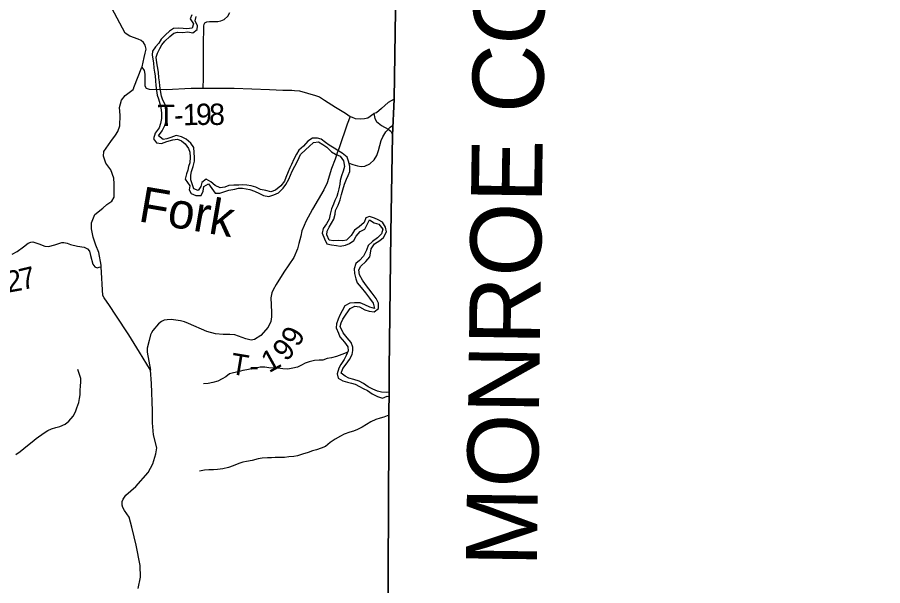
# Model space of a CAD drawing. Extents: x 2043100 to 2470832, y 443715 to 810583.
# Drawn here: x 2296048 to 2308244, y 667437 to 675442 of the extents above; entities that cross this region are included whole.
import ezdxf

# ---------------------------------------------------------------- set-up
doc = ezdxf.new("R2010")
doc.units = 0
for name, color, linetype in [('GM_X_Adjacent_County', 7, 'Continuous'), ('GM_X_Adjacent_County_Text', 7, 'Continuous'), ('GM_X_County', 7, 'Continuous'), ('GM_X_Minor_River', 7, 'Continuous'), ('GM_X_Minor_River_Text', 7, 'Continuous'), ('GM_X_State_Route', 7, 'Continuous'), ('GM_X_Township', 7, 'Continuous'), ('GM_X_Township_Road', 7, 'Continuous'), ('GM_X_Township_Road_Text', 7, 'Continuous'), ('GM_X_Township_ROW', 7, 'Continuous')]:
    doc.layers.add(name, color=color, linetype=linetype)

msp = doc.modelspace()

# ---------------------------------------------------------------- linework, layer by layer
at = {"layer": 'GM_X_Adjacent_County'}
msp.add_lwpolyline([(2300714, 629163), (2300774, 635425), (2300814, 639567), (2300926, 645360), (2300953, 646723), (2300982, 648198), (2301002, 649256), (2301016, 650156), (2301098, 653379), (2301153, 655541), (2301153, 656155), (2301254, 663815), (2301288, 670486), (2301311, 672396), (2301315, 672683), (2301334, 673782), (2301360, 674291), (2301434, 679295), (2301452, 681110), (2301478, 683091), (2302497, 683068), (2305696, 683037), (2309205, 683004)], dxfattribs=at)
at = {"layer": 'GM_X_County'}
msp.add_lwpolyline([(2309205, 683004), (2305696, 683037), (2302497, 683068), (2301478, 683091), (2301452, 681110), (2301434, 679295), (2301360, 674291), (2301334, 673782), (2301315, 672683), (2301311, 672396), (2301288, 670486), (2301254, 663815), (2301153, 656155), (2301153, 655541), (2301098, 653379), (2301016, 650156), (2301002, 649256), (2300982, 648198), (2300953, 646723), (2300926, 645360), (2300814, 639567), (2300774, 635425), (2300714, 629163)], dxfattribs=at)
at = {"layer": 'GM_X_Minor_River'}
msp.add_line((2301288, 670100), (2301289, 670163), dxfattribs=at)
for points in [[(2298537, 673607), (2298494, 673671), (2298426, 673724), (2298362, 673760), (2298286, 673776), (2298210, 673751), (2298156, 673731), (2298104, 673722), (2298036, 673772), (2298088, 673842), (2298125, 673917), (2298147, 673979), (2298152, 674051), (2298146, 674103), (2298138, 674165), (2298131, 674215), (2298097, 674277), (2298081, 674333), (2298066, 674413), (2298058, 674477), (2298050, 674533), (2298043, 674589), (2298037, 674667), (2298024, 674751), (2298016, 674801), (2298006, 674879), (2298025, 674938), (2298057, 675002), (2298087, 675054), (2298126, 675107), (2298196, 675173), (2298252, 675219), (2298307, 675234), (2298379, 675226), (2298449, 675235), (2298521, 675223), (2298583, 675268), (2298587, 675322), (2298554, 675392), (2298570, 675452)], [(2298506, 675475), (2298486, 675421), (2298529, 675351), (2298513, 675291), (2298439, 675281), (2298385, 675286), (2298321, 675288), (2298249, 675282), (2298195, 675247), (2298138, 675195), (2298076, 675132)], [(2298076, 675132), (2298041, 675078), (2297995, 675026), (2297953, 674965), (2297948, 674915), (2297958, 674851), (2297968, 674801), (2297971, 674725), (2297983, 674671), (2297991, 674619), (2297994, 674549), (2298000, 674481), (2298017, 674345), (2298037, 674293), (2298055, 674229), (2298072, 674167), (2298082, 674097), (2298081, 674019), (2298067, 673946), (2298047, 673884), (2297992, 673808), (2297968, 673732), (2298011, 673676), (2298081, 673666), (2298157, 673691), (2298238, 673715), (2298306, 673726), (2298360, 673700), (2298415, 673658), (2298459, 673596), (2298479, 673542), (2298486, 673474), (2298480, 673392), (2298460, 673342), (2298451, 673288), (2298433, 673238), (2298413, 673163), (2298478, 673070), (2298472, 673013), (2298500, 672962), (2298565, 672930), (2298637, 672930), (2298666, 672993), (2298678, 673059), (2298744, 673095), (2298790, 673031), (2298834, 672966), (2298904, 672966), (2298960, 672984), (2299030, 673007), (2299112, 673021), (2299164, 673036), (2299220, 673034), (2299272, 673028), (2299324, 673017), (2299390, 672995), (2299460, 672961), (2299518, 672934), (2299592, 672916), (2299662, 672940), (2299730, 672971), (2299795, 673035), (2299833, 673086), (2299876, 673164), (2299920, 673273), (2299959, 673345), (2300003, 673423), (2300038, 673510), (2300112, 673582), (2300163, 673623), (2300223, 673677), (2300291, 673687), (2300355, 673650), (2300409, 673612), (2300476, 673548), (2300530, 673515), (2300596, 673485), (2300646, 673421), (2300659, 673341), (2300639, 673275), (2300618, 673207), (2300600, 673144), (2300594, 673094), (2300579, 673024), (2300563, 672972), (2300551, 672920), (2300524, 672862), (2300502, 672811), (2300476, 672745), (2300459, 672669), (2300445, 672597), (2300406, 672532), (2300358, 672466), (2300346, 672400), (2300375, 672320), (2300411, 672250), (2300477, 672238), (2300545, 672227), (2300597, 672219), (2300675, 672234), (2300729, 672256)], [(2300724, 673390), (2300778, 673368), (2300841, 673348), (2300893, 673341), (2300946, 673345), (2301016, 673377), (2301076, 673434), (2301117, 673496), (2301137, 673566), (2301155, 673635), (2301176, 673709), (2301200, 673759), (2301241, 673827), (2301303, 673894), (2301335, 673919)], [(2301008, 671302), (2301078, 671294), (2301136, 671339), (2301140, 671417), (2301107, 671481), (2301051, 671559), (2301000, 671618), (2300954, 671678), (2300914, 671742), (2300871, 671814), (2300859, 671886), (2300891, 671936), (2300960, 672001), (2301016, 672067), (2301026, 672119), (2301033, 672182), (2301081, 672250), (2301156, 672297), (2301210, 672339), (2301252, 672419), (2301237, 672487), (2301195, 672557), (2301133, 672591), (2301081, 672615), (2301013, 672638), (2300961, 672616), (2300935, 672550), (2300865, 672491), (2300800, 672445), (2300752, 672370), (2300689, 672304), (2300635, 672295), (2300573, 672297), (2300505, 672295), (2300441, 672304), (2300412, 672380), (2300414, 672430), (2300442, 672488), (2300475, 672541), (2300507, 672597), (2300527, 672671), (2300534, 672721), (2300572, 672794), (2300597, 672870), (2300617, 672946), (2300637, 673012), (2300658, 673091), (2300686, 673161), (2300713, 673213), (2300733, 673269), (2300733, 673342), (2300722, 673402), (2300696, 673470), (2300628, 673527), (2300577, 673557), (2300513, 673599), (2300443, 673640), (2300393, 673678), (2300329, 673728), (2300279, 673741), (2300207, 673741), (2300141, 673699), (2300083, 673628), (2300014, 673570), (2299982, 673513), (2299943, 673445), (2299911, 673371), (2299891, 673320), (2299864, 673266), (2299834, 673186), (2299815, 673136), (2299761, 673067), (2299689, 673009), (2299620, 672984), (2299549, 673002), (2299475, 673019), (2299409, 673049), (2299343, 673067), (2299283, 673076), (2299227, 673082), (2299169, 673080), (2299099, 673079), (2299031, 673071), (2298972, 673051), (2298908, 673042), (2298834, 673072), (2298775, 673127), (2298709, 673161), (2298649, 673115), (2298636, 673061), (2298596, 673004), (2298538, 673028), (2298516, 673082), (2298495, 673154), (2298493, 673220), (2298505, 673270), (2298528, 673342), (2298546, 673415), (2298544, 673467), (2298539, 673539), (2298537, 673607)], [(2300729, 672256), (2300789, 672300), (2300824, 672361), (2300880, 672425), (2300946, 672460), (2300979, 672526), (2301013, 672590), (2301079, 672548), (2301145, 672529), (2301199, 672459), (2301180, 672391), (2301124, 672338), (2301055, 672286), (2300991, 672227), (2300967, 672161), (2300928, 672079), (2300872, 672018), (2300821, 671976), (2300795, 671898), (2300799, 671832), (2300818, 671758), (2300840, 671704), (2300896, 671636), (2300955, 671560), (2301011, 671486), (2301062, 671417), (2301080, 671343), (2301016, 671358), (2300946, 671394), (2300878, 671421), (2300802, 671423), (2300732, 671415), (2300666, 671380), (2300625, 671310), (2300593, 671245), (2300569, 671191), (2300548, 671125), (2300544, 671071), (2300574, 670995), (2300595, 670943), (2300659, 670867), (2300705, 670799), (2300712, 670745), (2300684, 670677), (2300655, 670623), (2300607, 670554), (2300577, 670500), (2300556, 670422), (2300572, 670362), (2300634, 670324), (2300702, 670305), (2300756, 670291), (2300810, 670273), (2300869, 670241), (2300923, 670216), (2300985, 670186), (2301051, 670140), (2301123, 670103), (2301195, 670079), (2301259, 670106), (2301288, 670100)], [(2301289, 670163), (2301249, 670160), (2301179, 670163), (2301123, 670179), (2301059, 670204), (2300991, 670238), (2300928, 670286), (2300866, 670318), (2300790, 670341), (2300720, 670361), (2300670, 670386), (2300610, 670430), (2300637, 670498), (2300683, 670559), (2300730, 670621), (2300768, 670694), (2300778, 670748), (2300775, 670798), (2300751, 670864), (2300699, 670930), (2300642, 670999), (2300598, 671087), (2300612, 671139), (2300637, 671192), (2300681, 671260), (2300738, 671342), (2300806, 671375), (2300872, 671363), (2300948, 671324), (2301008, 671302)], [(2300704, 670727), (2300622, 670695), (2300548, 670664), (2300475, 670648), (2300417, 670635), (2300355, 670615), (2300303, 670611), (2300237, 670608), (2300163, 670592), (2300107, 670571), (2300055, 670545), (2299996, 670517), (2299932, 670500), (2299862, 670486), (2299790, 670489), (2299726, 670501), (2299658, 670501), (2299594, 670506), (2299538, 670516), (2299470, 670513), (2299416, 670501), (2299348, 670489), (2299282, 670478), (2299227, 670466), (2299161, 670447), (2299097, 670437), (2299039, 670421), (2298985, 670380), (2298933, 670350), (2298872, 670316), (2298802, 670297), (2298738, 670283), (2298672, 670278)], [(2296028, 669285), (2296089, 669327), (2296141, 669370), (2296193, 669412), (2296255, 669463), (2296312, 669511), (2296424, 669592), (2296479, 669622), (2296531, 669645), (2296593, 669665), (2296649, 669679), (2296723, 669710), (2296776, 669754), (2296834, 669823), (2296868, 669885), (2296887, 669941), (2296915, 670015), (2296925, 670072), (2296934, 670126), (2296936, 670186), (2296939, 670250), (2296945, 670302), (2296941, 670356), (2296920, 670426), (2296900, 670482)], [(2301285, 669837), (2301215, 669811), (2301161, 669796), (2301103, 669780), (2301029, 669744), (2300968, 669709), (2300908, 669669), (2300844, 669638), (2300786, 669614), (2300732, 669597), (2300655, 669569), (2300601, 669541), (2300529, 669500), (2300456, 669452), (2300390, 669399), (2300332, 669375), (2300264, 669352), (2300206, 669336), (2300145, 669313), (2300069, 669291), (2299997, 669268), (2299945, 669258), (2299873, 669250), (2299813, 669243), (2299753, 669241), (2299683, 669241), (2299629, 669238), (2299573, 669236), (2299501, 669235), (2299444, 669223), (2299356, 669201), (2299280, 669188), (2299226, 669176), (2299168, 669157), (2299090, 669125), (2299025, 669100), (2298943, 669084), (2298871, 669073), (2298815, 669071), (2298747, 669071), (2298685, 669066), (2298617, 669052)]]:
    msp.add_lwpolyline(points, dxfattribs=at)
at = {"layer": 'GM_X_State_Route'}
for points in [[(2297689, 674449), (2297690, 674451), (2297804, 674740), (2297806, 674746), (2297835, 674877), (2297849, 674935), (2297865, 674994), (2297851, 675050), (2297824, 675088), (2297793, 675116), (2297752, 675135), (2297632, 675176), (2297570, 675218), (2297236, 675848), (2297073, 676138), (2296999, 676288), (2296974, 676392), (2296980, 676506), (2297162, 676814), (2297276, 677008), (2297962, 678256), (2299218, 680527), (2299695, 681368), (2300563, 682927)], [(2297752, 667396), (2297784, 667557), (2297777, 667720), (2297722, 668008), (2297693, 668124), (2297660, 668262), (2297645, 668334), (2297626, 668404), (2297559, 668497), (2297535, 668539), (2297527, 668571), (2297525, 668621), (2297539, 668657), (2297577, 668710), (2297718, 668835), (2297892, 669033), (2297959, 669152), (2297998, 669292), (2298012, 669380), (2297968, 669561), (2297955, 669729), (2297953, 669900), (2297940, 670287), (2297924, 670472), (2297768, 670725), (2297619, 670972), (2297436, 671249), (2297345, 671383), (2297272, 671490), (2297254, 671526), (2297229, 671929), (2297228, 671949), (2297197, 672130), (2297154, 672234), (2297119, 672346), (2297094, 672462), (2297093, 672548), (2297142, 672665), (2297252, 672754), (2297311, 672805), (2297379, 672851), (2297415, 672908), (2297415, 673096), (2297408, 673177), (2297365, 673292), (2297296, 673388), (2297261, 673484), (2297265, 673554), (2297368, 673692), (2297433, 673780), (2297465, 673833), (2297494, 673913), (2297497, 674064), (2297486, 674170), (2297514, 674277), (2297569, 674339), (2297681, 674426), (2297689, 674449)]]:
    msp.add_lwpolyline(points, dxfattribs=at)
at = {"layer": 'GM_X_Township'}
msp.add_lwpolyline([(2301434, 679295), (2301360, 674291), (2301334, 673782), (2301315, 672683), (2301311, 672396), (2301288, 670486), (2301254, 663815), (2301153, 656155)], dxfattribs=at)
at = {"layer": 'GM_X_Township_Road'}
for points in [[(2298667, 674442), (2298672, 674586), (2298674, 674793), (2298672, 675043), (2298675, 675316), (2298683, 675346), (2298693, 675362), (2298717, 675378), (2298757, 675381), (2298873, 675382), (2298917, 675394), (2298963, 675413), (2299013, 675457), (2299042, 675508)], [(2297804, 674740), (2297834, 674695), (2297844, 674643), (2297845, 674509), (2297846, 674475), (2297864, 674443), (2297908, 674431), (2298145, 674427), (2298499, 674446), (2298667, 674442), (2298765, 674443), (2299102, 674442), (2299603, 674424), (2299791, 674416), (2299915, 674417), (2299953, 674413), (2300027, 674406), (2300252, 674340), (2300307, 674324), (2300377, 674277), (2300534, 674176), (2300671, 674091), (2300738, 674045), (2300766, 674036), (2300808, 674018), (2300878, 674013), (2300940, 674017), (2300990, 674028), (2301073, 674089)], [(2301360, 674291), (2301273, 674241), (2301179, 674156), (2301110, 674095), (2301073, 674089)], [(2300738, 674045), (2300699, 673937), (2300583, 673605), (2300556, 673533), (2300527, 673442), (2300478, 673313), (2300414, 673112), (2300366, 673012), (2300207, 672742), (2300116, 672568), (2300089, 672510), (2300059, 672437), (2300042, 672359), (2300015, 672257), (2299997, 672180), (2299944, 672060), (2299804, 671854), (2299696, 671678), (2299652, 671602), (2299635, 671560), (2299621, 671489), (2299629, 671289), (2299630, 671223), (2299622, 671160), (2299583, 671076), (2299478, 670959), (2299390, 670904), (2299346, 670897), (2299268, 670913), (2299165, 670952), (2299113, 670971), (2299045, 670977), (2298951, 670974), (2298841, 670983), (2298718, 671018), (2298459, 671132), (2298405, 671154), (2298346, 671169), (2298216, 671184), (2298160, 671183), (2298116, 671175), (2298080, 671159), (2298038, 671124), (2297957, 671029), (2297937, 670999), (2297926, 670969), (2297904, 670892), (2297877, 670780), (2297878, 670728), (2297924, 670472)], [(2301073, 674089), (2301088, 674019), (2301109, 673976), (2301180, 673920), (2301273, 673867), (2301311, 673838), (2301326, 673811), (2301334, 673782), (2301333, 673722)], [(2301333, 673722), (2301317, 672805)], [(2295975, 672108), (2296048, 672145), (2296134, 672210), (2296203, 672263), (2296237, 672277), (2296265, 672279), (2296350, 672250), (2296438, 672217), (2296488, 672215), (2296578, 672238), (2296648, 672263), (2296676, 672271), (2296704, 672271), (2296750, 672262), (2296799, 672240), (2296895, 672217), (2296989, 672206), (2297039, 672180), (2297064, 672148), (2297080, 672088), (2297111, 671966), (2297140, 671928), (2297172, 671914), (2297200, 671921), (2297229, 671929)]]:
    msp.add_lwpolyline(points, dxfattribs=at)
at = {"layer": 'GM_X_Township_ROW'}
msp.add_lwpolyline([(2301317, 672805), (2301315, 672683), (2301311, 672396), (2301288, 670486)], dxfattribs=at)

# ---------------------------------------------------------------- texts
at = {"layer": 'GM_X_Adjacent_County_Text'}
msp.add_text('MONROE COUNTY', height=1000, rotation=89.2055, dxfattribs=at).set_placement((2303370, 667699))
at = {"layer": 'GM_X_Minor_River_Text'}
msp.add_text('Fork', height=500, rotation=350.2453, dxfattribs=at).set_placement((2297741, 672571))
at = {"layer": 'GM_X_Township_Road_Text'}
for s, rotation, p in [('9', 0.3851, (2298567, 673925)), ('8', 0.026, (2298751, 673926)), ('T', 1.2258, (2298029, 673909)), ('1', 1.5666, (2298384, 673920)), ('-', 2.8663, (2298263, 673914)), ('7', 13.2954, (2296113, 671598)), ('2', 10.1985, (2295914, 671562)), ('9', 61.699, (2300009, 670784)), ('9', 47.3906, (2299837, 670582)), ('T', 350.4285, (2299036, 670423)), ('1', 29.1129, (2299594, 670427)), ('-', 2.2098, (2299324, 670382))]:
    msp.add_text(s, height=300, rotation=rotation, dxfattribs=at).set_placement(p)

doc.saveas('drawing.dxf')
